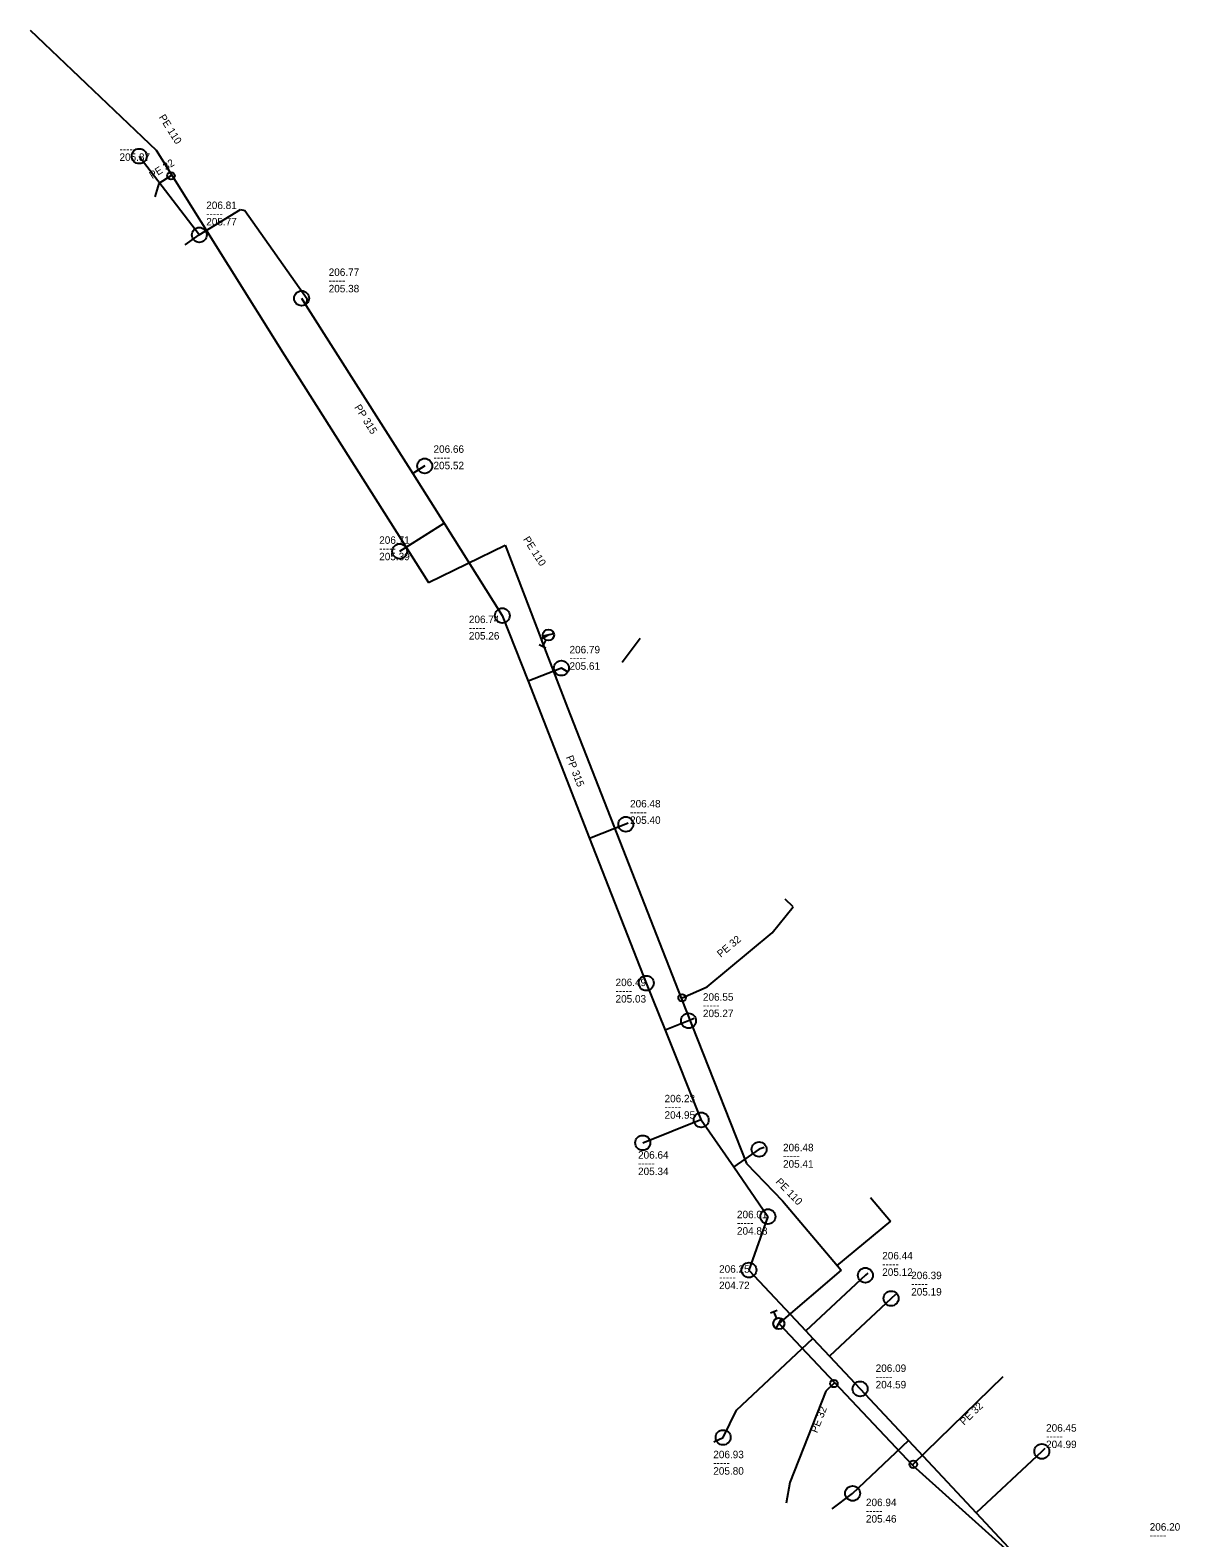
# Model space of a CAD drawing. Extents: x -695225 to -694112, y -1052622 to -1052029.
# Drawn here: x -695224.7 to -695070.7, y -1052231.3 to -1052029.3 of the extents above; entities that cross this region are included whole.
import ezdxf

# ---------------------------------------------------------------- set-up
doc = ezdxf.new("R2010")
doc.units = 0
doc.layers.add('Level 0', color=7, linetype='Continuous')

msp = doc.modelspace()

# ---------------------------------------------------------------- linework, layer by layer
at = {"layer": 'Level 0'}
for p, q in [((-695224.74, -1052029.34), (-695207.86, -1052045.41)), ((-695207.86, -1052045.41), (-695205.75, -1052048.77)), ((-695210.13, -1052046.22), (-695202.07, -1052056.77)), ((-695205.88, -1052048.85), (-695207.49, -1052049.86)), ((-695205.75, -1052048.77), (-695205.88, -1052048.85)), ((-695205.75, -1052048.77), (-695190.67, -1052072.87)), ((-695207.49, -1052049.86), (-695208.02, -1052051.66)), ((-695202.08, -1052056.77), (-695196.58, -1052053.35)), ((-695196.58, -1052053.35), (-695195.98, -1052053.48)), ((-695195.98, -1052053.48), (-695187.63, -1052065.32)), ((-695203.98, -1052058.1), (-695202.08, -1052056.77)), ((-695188.38, -1052065.26), (-695187.79, -1052066.19)), ((-695187.63, -1052065.32), (-695187.79, -1052066.19)), ((-695187.79, -1052066.19), (-695173.47, -1052088.71)), ((-695190.67, -1052072.87), (-695171.4, -1052103.33)), ((-695171.89, -1052087.71), (-695173.47, -1052088.71)), ((-695173.47, -1052088.71), (-695169.27, -1052095.4)), ((-695175.24, -1052099.15), (-695169.27, -1052095.4)), ((-695169.27, -1052095.4), (-695161.49, -1052107.77)), ((-695171.4, -1052103.33), (-695161.12, -1052098.32)), ((-695161.12, -1052098.32), (-695156.3, -1052110.91)), ((-695161.49, -1052107.77), (-695158.05, -1052116.55)), ((-695155.66708, -1052112.14465), (-695156.55602, -1052111.68663)), ((-695155.31, -1052110.36), (-695156.3, -1052110.91)), ((-695156.3, -1052110.91), (-695156.28, -1052110.96)), ((-695156.28, -1052110.96), (-695152.77, -1052120.13)), ((-695155.65352, -1052111.0267), (-695156.11155, -1052111.91564)), ((-695154.5757, -1052110.21863), (-695156.04878, -1052110.50131)), ((-695145.43, -1052114.02), (-695143.04, -1052110.8)), ((-695153.58, -1052114.8), (-695158.05, -1052116.55)), ((-695152.69, -1052115.33), (-695153.58, -1052114.8)), ((-695158.05, -1052116.55), (-695149.8, -1052137.62)), ((-695152.77, -1052120.13), (-695137.55, -1052159.02)), ((-695144.95, -1052135.72), (-695149.8, -1052137.62)), ((-695144.64, -1052135.59), (-695144.95, -1052135.72)), ((-695149.8, -1052137.62), (-695142.21, -1052157)), ((-695122.51, -1052146.79), (-695123.62, -1052145.73)), ((-695125.36, -1052150.26), (-695122.51, -1052146.79)), ((-695134.05, -1052157.51), (-695125.36, -1052150.26)), ((-695142.21, -1052157), (-695139.68, -1052163.3)), ((-695137.41, -1052158.96), (-695134.05, -1052157.51)), ((-695137.55, -1052159.02), (-695137.41, -1052158.96)), ((-695137.55, -1052159.02), (-695128.79, -1052181.15)), ((-695136.55, -1052162.04), (-695139.68, -1052163.3)), ((-695135.77, -1052161.72), (-695136.55, -1052162.04)), ((-695139.68, -1052163.3), (-695134.88, -1052175.26)), ((-695142.68, -1052178.39), (-695134.88, -1052175.26)), ((-695134.88, -1052175.26), (-695134.85, -1052175.32)), ((-695134.85, -1052175.32), (-695130.5, -1052181.62)), ((-695127.09, -1052179.26), (-695130.5, -1052181.62)), ((-695126.4, -1052179.01), (-695127.09, -1052179.26)), ((-695130.5, -1052181.62), (-695125.91, -1052188.27)), ((-695128.79, -1052181.15), (-695123.94, -1052186.17)), ((-695123.94, -1052186.17), (-695116.1, -1052195.43)), ((-695112.16, -1052185.7), (-695109.51, -1052188.89)), ((-695125.91, -1052188.27), (-695128.46, -1052195.43)), ((-695109.51, -1052188.89), (-695116.72, -1052194.88)), ((-695128.46, -1052195.43), (-695120.83, -1052203.58)), ((-695116.1, -1052195.43), (-695124.45, -1052202.6)), ((-695112.86, -1052196.13), (-695120.83, -1052203.58)), ((-695112.53, -1052195.83), (-695112.86, -1052196.13)), ((-695108.81, -1052198.7), (-695109.41, -1052199.24)), ((-695125.58425, -1052201.17663), (-695124.66107, -1052200.79225)), ((-695124.73828, -1052201.90762), (-695125.12266, -1052200.98444)), ((-695109.41, -1052199.24), (-695117.66, -1052206.96)), ((-695124.81525, -1052203.25252), (-695124.08183, -1052201.9441)), ((-695124.45, -1052202.6), (-695106.55, -1052221.56)), ((-695130.12, -1052214.19), (-695119.9, -1052204.58)), ((-695120.83, -1052203.58), (-695119.9, -1052204.58)), ((-695119.9, -1052204.58), (-695117.66, -1052206.96)), ((-695117.66, -1052206.96), (-695113.56, -1052211.35)), ((-695117.07, -1052210.64), (-695118.16, -1052211.67)), ((-695116.96, -1052210.54), (-695117.07, -1052210.64)), ((-695106.44, -1052221.45), (-695094.4, -1052209.67)), ((-695118.16, -1052211.67), (-695122.97, -1052223.9)), ((-695113.56, -1052211.35), (-695107.07, -1052218.28)), ((-695131.91, -1052217.86), (-695130.12, -1052214.19)), ((-695133.14, -1052218.44), (-695131.91, -1052217.86)), ((-695114.57, -1052225.35), (-695107.07, -1052218.28)), ((-695107.07, -1052218.28), (-695098.02, -1052227.95)), ((-695089.22, -1052219.72), (-695098.02, -1052227.95)), ((-695088.84, -1052219.34), (-695089.22, -1052219.72)), ((-695106.55, -1052221.56), (-695106.44, -1052221.45)), ((-695106.55, -1052221.56), (-695074.65, -1052250.23)), ((-695122.97, -1052223.9), (-695123.49, -1052226.66)), ((-695117.29, -1052227.41), (-695114.57, -1052225.35)), ((-695098.02, -1052227.95), (-695090.54, -1052235.95))]:
    msp.add_line(p, q, dxfattribs=at)
for centre, radius in [((-695210.13, -1052046.22), 1), ((-695205.88, -1052048.85), 0.5), ((-695202.08, -1052056.77), 1), ((-695188.38, -1052065.26), 1), ((-695171.89, -1052087.71), 1), ((-695175.24, -1052099.15), 1), ((-695161.49, -1052107.77), 1), ((-695155.31, -1052110.36), 0.75), ((-695153.58, -1052114.8), 1), ((-695144.95, -1052135.72), 1), ((-695142.21, -1052157), 1), ((-695137.41, -1052158.96), 0.5), ((-695136.55, -1052162.04), 1), ((-695134.85, -1052175.32), 1), ((-695142.68, -1052178.39), 1), ((-695127.09, -1052179.26), 1), ((-695125.91, -1052188.27), 1), ((-695128.46, -1052195.43), 1), ((-695112.86, -1052196.13), 1), ((-695109.41, -1052199.24), 1), ((-695124.45, -1052202.6), 0.75), ((-695117.07, -1052210.64), 0.5), ((-695113.56, -1052211.35), 1), ((-695131.91, -1052217.86), 1), ((-695089.22, -1052219.72), 1), ((-695106.44, -1052221.45), 0.5), ((-695114.57, -1052225.35), 1)]:
    msp.add_circle(centre, radius, dxfattribs=at)

# ---------------------------------------------------------------- texts
for s, rotation, p in [('PE 110', 302.319, (-695207.55, -1052041.01)), ('PE 32', 32.101, (-695208.39, -1052049.31)), ('PP 315', 302.121, (-695181.35, -1052079.86)), ('PE 110', 302.319, (-695158.75, -1052097.54)), ('PP 315', 291.383, (-695152.99, -1052126.72)), ('PE 32', 39.838, (-695132.22, -1052153.62)), ('PE 110', 314.013, (-695124.95, -1052183.68)), ('PE 32', 44.375, (-695099.62, -1052216.29)), ('PE 32', 68.531, (-695119.32, -1052217.33))]:
    msp.add_text(s, height=1, rotation=rotation, dxfattribs=at).set_placement(p)
for s, p in [('-----', (-695212.77, -1052045.75)), ('205.87', (-695212.77, -1052046.85)), ('206.81', (-695201.15, -1052053.3)), ('-----', (-695201.15, -1052054.4)), ('205.77', (-695201.15, -1052055.5)), ('206.77', (-695184.75, -1052062.26)), ('-----', (-695184.75, -1052063.36)), ('205.38', (-695184.75, -1052064.46)), ('206.66', (-695170.71, -1052085.96)), ('-----', (-695170.71, -1052087.06)), ('205.52', (-695170.71, -1052088.16)), ('206.71', (-695177.98, -1052098.15)), ('-----', (-695177.98, -1052099.25)), ('205.39', (-695177.98, -1052100.35)), ('206.74', (-695165.97, -1052108.77)), ('-----', (-695165.97, -1052109.87)), ('205.26', (-695165.97, -1052110.97)), ('206.79', (-695152.49, -1052112.82)), ('-----', (-695152.49, -1052113.92)), ('205.61', (-695152.49, -1052115.02)), ('-----', (-695144.38, -1052134.56)), ('206.48', (-695144.38, -1052133.46)), ('205.40', (-695144.38, -1052135.66)), ('206.49', (-695146.32, -1052157.4)), ('-----', (-695146.32, -1052158.5)), ('205.03', (-695146.32, -1052159.6)), ('206.55', (-695134.62, -1052159.35)), ('-----', (-695134.62, -1052160.45)), ('205.27', (-695134.62, -1052161.55)), ('206.23', (-695139.76, -1052172.96)), ('-----', (-695139.76, -1052174.06)), ('204.95', (-695139.76, -1052175.16)), ('206.48', (-695123.89, -1052179.52)), ('206.64', (-695143.31, -1052180.51)), ('-----', (-695123.89, -1052180.62)), ('205.41', (-695123.89, -1052181.72)), ('-----', (-695143.31, -1052181.61)), ('205.34', (-695143.31, -1052182.71)), ('206.01', (-695130.06, -1052188.49)), ('-----', (-695130.06, -1052189.59)), ('204.88', (-695130.06, -1052190.69)), ('206.25', (-695132.45, -1052195.79)), ('-----', (-695110.6, -1052195.11)), ('206.44', (-695110.6, -1052194.01)), ('-----', (-695132.45, -1052196.89)), ('204.72', (-695132.45, -1052197.99)), ('205.12', (-695110.6, -1052196.21)), ('206.39', (-695106.72, -1052196.65)), ('-----', (-695106.72, -1052197.75)), ('205.19', (-695106.72, -1052198.85)), ('206.09', (-695111.48, -1052209.08)), ('-----', (-695111.48, -1052210.18)), ('204.59', (-695111.48, -1052211.28)), ('206.45', (-695088.65, -1052217.08)), ('-----', (-695088.65, -1052218.18)), ('204.99', (-695088.65, -1052219.28)), ('206.93', (-695133.23, -1052220.64)), ('-----', (-695133.23, -1052221.74)), ('205.80', (-695133.23, -1052222.84)), ('206.94', (-695112.78, -1052227.06)), ('-----', (-695112.78, -1052228.16)), ('205.46', (-695112.78, -1052229.26)), ('206.20', (-695074.77, -1052230.34)), ('-----', (-695074.77, -1052231.44))]:
    msp.add_text(s, height=1, dxfattribs=at).set_placement(p)

doc.saveas('drawing.dxf')
